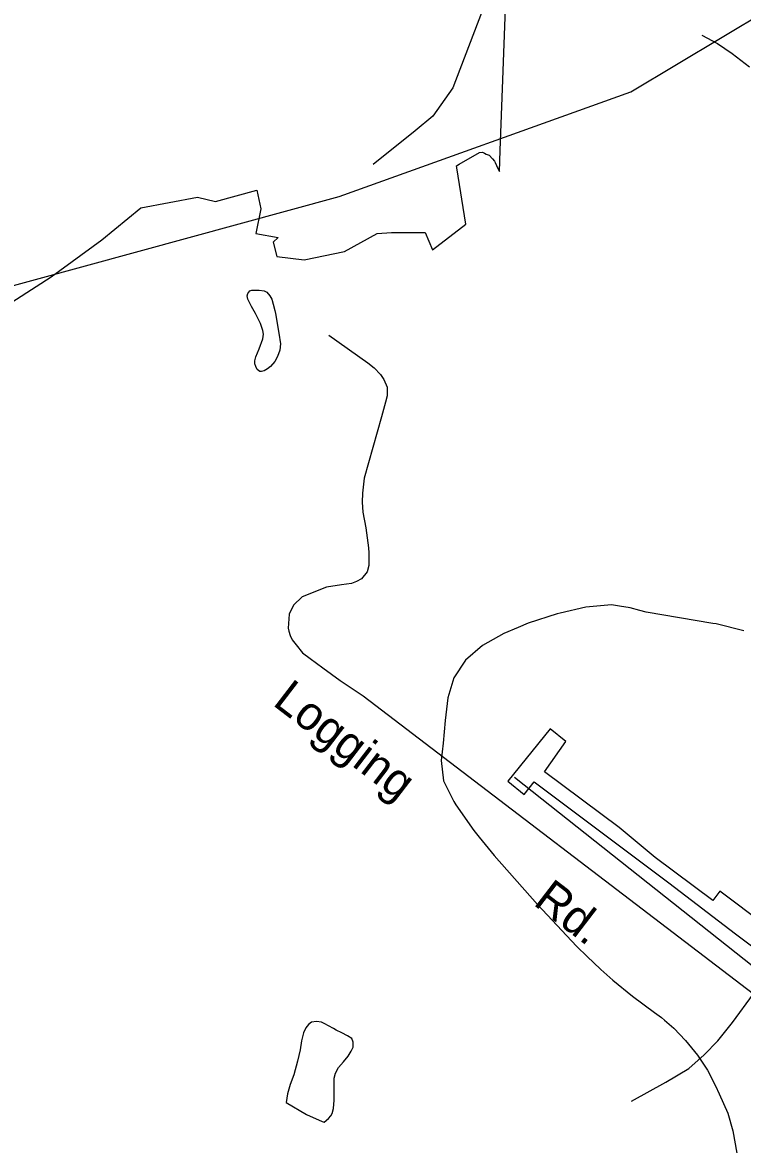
# Model space of a CAD drawing. Extents: x 2001466 to 2224147, y 644118 to 847247.
# Drawn here: x 2043610 to 2045643, y 687083 to 690251 of the extents above; entities that cross this region are included whole.
import ezdxf

# ---------------------------------------------------------------- set-up
doc = ezdxf.new("R2010")
doc.units = 0
for name, color, linetype in [('Exist Boundary Political City Limit New', 7, 'Continuous'), ('Exist Hydrographic Creek Single Shore', 7, 'Continuous'), ('Exist Hydrographic Misc Water Feature', 7, 'Continuous'), ('Exist Road Non-System Type 51', 7, 'Continuous'), ('Exist Road Non-System Type 51 Label', 7, 'Continuous'), ('Map Preparation Boundary City Limit Buffer Line', 7, 'Continuous')]:
    doc.layers.add(name, color=color, linetype=linetype)

msp = doc.modelspace()

# ---------------------------------------------------------------- linework, layer by layer
at = {"layer": 'Exist Boundary Political City Limit New'}
for points in [[(2044835, 689846.6), (2044842.9, 689851.1), (2044900.8, 689884.4), (2044909.1, 689884.7), (2044914.5, 689882.5), (2044918.8, 689879.3), (2044927.8, 689876.4), (2044937.2, 689866.1), (2044942.6, 689859.2), (2044945, 689855.4), (2044948.5, 689847.6), (2044951.1, 689840.3), (2044956.9, 689830.8), (2044959, 689889.5), (2044966.4, 690089.1), (2044973.9, 690291.7)], [(2043536.1, 689433.8), (2043691.1, 689533.4), (2043833.6, 689637.8), (2043944.5, 689727.9), (2044023.9, 689742.9), (2044104.2, 689758), (2044154.9, 689746.1), (2044271.5, 689777.8), (2044283.2, 689725.4), (2044268.4, 689655.2), (2044331.5, 689644.1), (2044318, 689631), (2044328.2, 689590.5), (2044405.1, 689580.6), (2044518.8, 689604.4), (2044611.2, 689655.2), (2044652.2, 689657.8), (2044701.2, 689658.2), (2044747.1, 689658.6), (2044767.2, 689608.8), (2044861.4, 689681.7), (2044835.9, 689840.8), (2044835, 689846.6)]]:
    msp.add_lwpolyline(points, dxfattribs=at)
at = {"layer": 'Exist Hydrographic Creek Single Shore'}
for points in [[(2042866.1, 689196.4), (2042905, 689208.6), (2043363.1, 689448.6), (2044504, 689760.1), (2045328.1, 690055.1), (2045714.7, 690286.8)], [(2047822.9, 684802.5), (2047762.9, 684808.5), (2047728.8, 684842), (2047654, 685083.1), (2047569.9, 685242.2), (2047378, 685449.5), (2047152.9, 685624.7), (2046968.9, 685848.3), (2046860.9, 686057.2), (2046727, 686266.6), (2046584.9, 686430.3), (2046425.9, 686689.4), (2046383.9, 686874), (2046383.9, 686998.7), (2046350.9, 687048.6), (2044999, 688119.4)]]:
    msp.add_lwpolyline(points, dxfattribs=at)
at = {"layer": 'Exist Hydrographic Misc Water Feature'}
for p, q in [((2045128.4, 688583.5), (2045120, 688581.6)), ((2044803.2, 688280.6), (2044798, 688216.6)), ((2044828, 688052), (2044833.1, 688041.8))]:
    msp.add_line(p, q, dxfattribs=at)
for points in [[(2045528.2, 690215.7), (2045572.5, 690191.9), (2045614.3, 690163.9), (2045662.5, 690126.1)], [(2044324.2, 689429.6), (2044334.2, 689373.7), (2044338.1, 689343.6), (2044336.3, 689325.6), (2044330.3, 689307.6), (2044322.3, 689293.7), (2044310.2, 689279.6), (2044302.2, 689273.6), (2044292.4, 689267.6), (2044284.4, 689265.6), (2044280.3, 689265.5), (2044272.3, 689271.5), (2044268.4, 689279.6), (2044266.3, 689287.6), (2044266.3, 689295.5), (2044268.4, 689307.5), (2044278.2, 689329.5), (2044288.3, 689357.5), (2044290.1, 689371.5), (2044288.3, 689381.5), (2044282.1, 689401.5), (2044268, 689429.5), (2044256.1, 689449.5), (2044246, 689469.5), (2044244, 689479.5), (2044246, 689485.5), (2044252, 689493.5), (2044257.9, 689495.5), (2044278, 689495.5), (2044292, 689493.5), (2044300, 689489.5), (2044308, 689479.6), (2044313.9, 689469.6), (2044318, 689455.6), (2044322.1, 689437.6), (2044324.2, 689429.6)], [(2045231.7, 688602.9), (2045201, 688600.1), (2045128.4, 688583.5)], [(2045231.7, 688602.9), (2045201, 688600.1), (2045128.4, 688583.5)], [(2045295.3, 688603.4), (2045272.9, 688606.8), (2045231.7, 688602.9)], [(2045295.3, 688603.4), (2045272.9, 688606.8), (2045231.7, 688602.9)], [(2045352.9, 688591.3), (2045326, 688598.8), (2045295.3, 688603.4)], [(2045352.9, 688591.3), (2045326, 688598.8), (2045295.3, 688603.4)], [(2045120, 688581.6), (2045038.2, 688555.1), (2045009.9, 688543.2)], [(2045120, 688581.6), (2045038.2, 688555.1), (2045009.9, 688543.2)], [(2045559, 688554.5), (2045371, 688586.1), (2045352.9, 688591.3)], [(2045559, 688554.5), (2045371, 688586.1), (2045352.9, 688591.3)], [(2045009.9, 688543.2), (2044969, 688526.1), (2044909, 688491.9)], [(2045009.9, 688543.2), (2044969, 688526.1), (2044909, 688491.9)], [(2045647, 688533.7), (2045568.2, 688552.9), (2045559, 688554.5)], [(2044909, 688491.9), (2044861, 688450.7), (2044828, 688401.1)], [(2044909, 688491.9), (2044861, 688450.7), (2044828, 688401.1)], [(2044828, 688401.1), (2044810.7, 688344.1), (2044803.2, 688280.6)], [(2044828, 688401.1), (2044810.7, 688344.1), (2044803.2, 688280.6)], [(2045811.2, 687572.6), (2045836.8, 687604.8), (2045578.9, 687798.5), (2045558.8, 687772.3), (2045396.8, 687893.9), (2045294.7, 687977.9), (2045084.1, 688135.2), (2045144, 688221.4), (2045100.3, 688257.2), (2044980.3, 688109.1), (2045026.3, 688071.3), (2045054.3, 688107.2), (2045272.7, 687943.5), (2045434.9, 687821.9), (2045623, 687678.3), (2045792.9, 687550.7), (2045811.2, 687572.6)], [(2044798, 688216.6), (2044791.9, 688167.3), (2044798.9, 688109.5), (2044828, 688052)], [(2044798, 688216.6), (2044791.9, 688167.3), (2044798.9, 688109.5), (2044828, 688052)], [(2044833.1, 688041.8), (2044884, 687970), (2044899.5, 687951)], [(2044833.1, 688041.8), (2044884, 687970), (2044899.5, 687951)], [(2044899.5, 687951), (2044942, 687899.1), (2045064, 687760.6), (2045173.9, 687643.3), (2045205.5, 687612.8)], [(2044899.5, 687951), (2044942, 687899.1), (2045064, 687760.6), (2045173.9, 687643.3), (2045205.5, 687612.8)], [(2045205.5, 687612.8), (2045222.3, 687596.6), (2045243.4, 687577.5)], [(2045205.5, 687612.8), (2045222.3, 687596.6), (2045243.4, 687577.5)], [(2045243.4, 687577.5), (2045277, 687547.5), (2045332, 687501.9), (2045394.3, 687456.2)], [(2045243.4, 687577.5), (2045277, 687547.5), (2045332, 687501.9), (2045394.3, 687456.2)], [(2045394.3, 687456.2), (2045414, 687441.8), (2045422.6, 687434.3)], [(2045394.3, 687456.2), (2045414, 687441.8), (2045422.6, 687434.3)], [(2044412.3, 687168.2), (2044456.2, 687148.3), (2044462.2, 687146.3), (2044474.3, 687156.3), (2044480.2, 687164.3), (2044484.3, 687170.3), (2044488.2, 687184.3), (2044490, 687208.3), (2044490, 687234.3), (2044490, 687270.3), (2044493.9, 687284.3), (2044501.9, 687300.3), (2044515.9, 687316.3), (2044529.8, 687332.3), (2044537.8, 687346.4), (2044543.8, 687358.4), (2044543.8, 687372.4), (2044539.7, 687382.4), (2044527.8, 687390.4), (2044511.8, 687398.4), (2044495.8, 687406.3), (2044487.8, 687410.3), (2044473.8, 687418.2), (2044463.8, 687424.2), (2044453.8, 687428.2), (2044439.8, 687430.1), (2044425.7, 687428.1), (2044417.7, 687422.1), (2044409.7, 687412.1), (2044403.7, 687398.1), (2044397.8, 687376.1), (2044393.9, 687350.1), (2044386.1, 687318.1), (2044376, 687280.1), (2044366.2, 687252.1), (2044358.2, 687226), (2044354.1, 687202), (2044412.3, 687168.2)], [(2045422.6, 687434.3), (2045449.1, 687411.5), (2045481.9, 687376.8)], [(2045422.6, 687434.3), (2045449.1, 687411.5), (2045481.9, 687376.8)], [(2045481.9, 687376.8), (2045515.7, 687335.6), (2045543.8, 687292.8)], [(2045481.9, 687376.8), (2045515.7, 687335.6), (2045543.8, 687292.8)], [(2045543.8, 687292.8), (2045567, 687248.8), (2045577.2, 687226.1)], [(2045543.8, 687292.8), (2045567, 687248.8), (2045577.2, 687226.1)], [(2045577.2, 687226.1), (2045602, 687171.7), (2045616, 687121.3)], [(2045577.2, 687226.1), (2045602, 687171.7), (2045616, 687121.3)], [(2045616, 687121.3), (2045626.9, 687059.1), (2045640, 686935.9), (2045639, 686888.5), (2045635.1, 686860.3)], [(2045616, 687121.3), (2045626.9, 687059.1), (2045640, 686935.9), (2045639, 686888.5), (2045635.1, 686860.3)]]:
    msp.add_lwpolyline(points, dxfattribs=at)
at = {"layer": 'Exist Road Non-System Type 51'}
for points in [[(2044918.7, 690310.2), (2044825.2, 690066.8), (2044768.8, 689986.6), (2044718.4, 689945.1), (2044599.7, 689850)], [(2044474.8, 689368.3), (2044585.2, 689290.1), (2044603, 689275.7), (2044620.6, 689257.3), (2044630.3, 689243.1), (2044639.8, 689221), (2044639.3, 689197), (2044635, 689179.1), (2044624.1, 689137.3), (2044574.6, 688964.3), (2044569.7, 688922.4), (2044569.2, 688896.4), (2044570.6, 688868.4), (2044579.7, 688824.2), (2044586.6, 688768), (2044588.3, 688754), (2044587.9, 688736), (2044587.6, 688718), (2044583.2, 688700.1), (2044566.8, 688680.4), (2044552.6, 688672.7), (2044538.5, 688667), (2044510.5, 688663.6), (2044468.3, 688656.4), (2044399.8, 688629.8), (2044375.3, 688606.3), (2044362.8, 688580.6), (2044359.9, 688540.6), (2044361.8, 688532.6), (2044365.5, 688520.5), (2044371.3, 688508.4), (2044383, 688494.2), (2044400.5, 688471.8), (2044422.2, 688455.4), (2044457.7, 688428.6), (2044506.9, 688393.6), (2044572.1, 688350.3), (2045673.9, 687508.5)], [(2045330, 687205.2), (2045426.5, 687259.3), (2045491.5, 687298), (2045534.8, 687336.7), (2045573.4, 687375.4), (2045615.2, 687428), (2045673.9, 687508.5)]]:
    msp.add_lwpolyline(points, dxfattribs=at)
at = {"layer": 'Map Preparation Boundary City Limit Buffer Line'}
for points in [[(2044835, 689846.6), (2044842.9, 689851.1), (2044900.8, 689884.4), (2044909.1, 689884.7), (2044914.5, 689882.5), (2044918.8, 689879.3), (2044927.8, 689876.4), (2044937.2, 689866.1), (2044942.6, 689859.2), (2044945, 689855.4), (2044948.5, 689847.6), (2044951.1, 689840.3), (2044956.9, 689830.8), (2044959, 689889.5), (2044966.4, 690089.1), (2044973.9, 690291.7)], [(2043536.1, 689433.8), (2043691.1, 689533.4), (2043833.6, 689637.8), (2043944.5, 689727.9), (2044023.9, 689742.9), (2044104.2, 689758), (2044154.9, 689746.1), (2044271.5, 689777.8), (2044283.2, 689725.4), (2044268.4, 689655.2), (2044331.5, 689644.1), (2044318, 689631), (2044328.2, 689590.5), (2044405.1, 689580.6), (2044518.8, 689604.4), (2044611.2, 689655.2), (2044652.2, 689657.8), (2044701.2, 689658.2), (2044747.1, 689658.6), (2044767.2, 689608.8), (2044861.4, 689681.7), (2044835.9, 689840.8), (2044835, 689846.6)]]:
    msp.add_lwpolyline(points, dxfattribs=at)

# ---------------------------------------------------------------- texts
at = {"layer": 'Exist Road Non-System Type 51 Label'}
for s, p in [('Logging', (2044313.2, 688325.9)), ('Rd.', (2045049.2, 687761.8))]:
    msp.add_text(s, height=95, rotation=322.5326, dxfattribs=at).set_placement(p)

doc.saveas('drawing.dxf')
